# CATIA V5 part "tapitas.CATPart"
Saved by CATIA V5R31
Part number: tapitas
Bounding box of the stored display mesh (mm): x -61 to 55, y -81 to 81, z 0 to 3.3
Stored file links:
  C:\Users\189361\Desktop\piezas del comedero\piezas del comedero\tapitas.CATPart
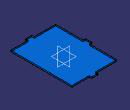
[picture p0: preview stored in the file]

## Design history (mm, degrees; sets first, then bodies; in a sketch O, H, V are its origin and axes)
Body1 (main body)
  Sketch1 on xy-plane, origin (0, 0, 0), H (1, 0, 0), V (0, 1, 0)
    point P1 (-2.5, -81)
    line L1 (-2.5, -81) -> (-2.5, -75)
    point P2 (-2.5, -75)
    line L2 (-2.5, -75) -> (-55, -75)
    point P3 (-55, -75)
    line L3 (-55, -75) -> (-55, -7.5)
    point P4 (-55, -7.5)
    line L4 (-55, -7.5) -> (-61, -7.5)
    point P5 (-61, -7.5)
    line L5 (-61, -7.5) -> (-61, 0)
    point P6 (-61, 0)
    point P7 (-2.5, 81)
    point P8 (-2.5, 75)
    point P9 (-55, 75)
    point P10 (-55, 7.5)
    point P11 (-61, 7.5)
    point P12 (-61, 0)
    line L6 (-2.5, 81) -> (-2.5, 75)
    line L7 (-2.5, 75) -> (-55, 75)
    line L8 (-55, 75) -> (-55, 7.5)
    line L9 (-55, 7.5) -> (-61, 7.5)
    line L10 (-61, 7.5) -> (-61, 0)
    line L11 (-2.5, -81) -> (12.5, -81)
    line L12 (12.5, -81) -> (12.5, -75)
    point P14 (12.5, -75)
    line L13 (12.5, -75) -> (55, -75)
    line L14 (55, -75) -> (55, 75)
    point P16 (55, 75)
    line L15 (55, 75) -> (12.5, 75)
    line L16 (12.5, 75) -> (12.5, 81)
    line L17 (12.5, 81) -> (-2.5, 81)
    distance L2 H = 75
    distance L3 V = 55
    length L4 = 6
    length L1 = 6
    length L5 = 7.5
    distance L1 L3 = 52.5
    length L11 = 15
    distance L3 L14 = 110
    vertical: L1 V, L3 V, L5 V, L12 V, L14 V, L16 V
    horizontal: L2 H, L4 H, L11 H, L13 H, L15 H, L17 H
    coincidence: P6 H, P6 P12, P14 L2, P16 L7
    symmetry: P1 P7 H, P2 P8 H, P3 P9 H, P4 P10 H, P5 P11 H, P6 P12 H, L1 L6 H, L2 L7 H, L3 L8 H, L4 L9 H, L5 L10 H
    equal size: L11 L17
  Pad1: profile Sketch1, direction (0, 0, 1), length 3.3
